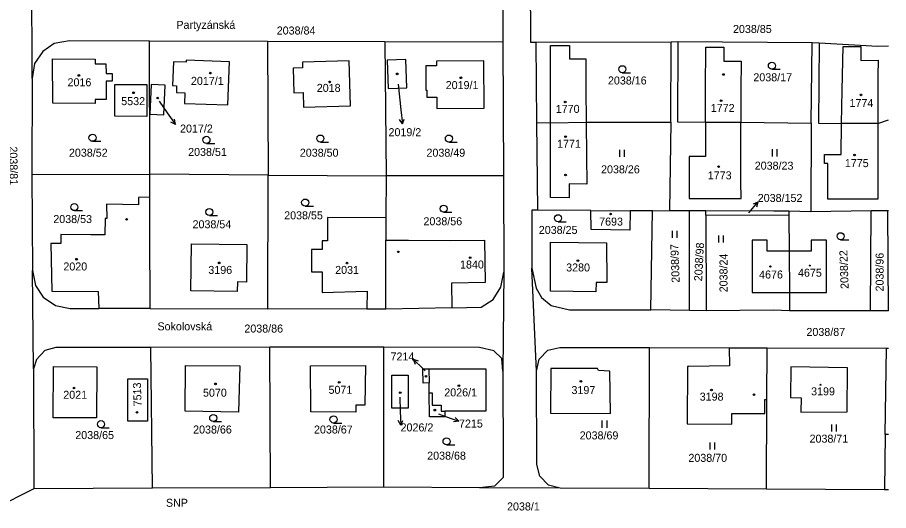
# Model space of a CAD drawing. Extents: x -667048 to -665920, y -1108425 to -1107247.
# Drawn here: x -666112.2 to -665927.3, y -1108016.4 to -1107911.7 of the extents above; entities that cross this region are included whole.
import ezdxf

# ---------------------------------------------------------------- set-up
doc = ezdxf.new("R2010")
doc.units = 0
for name, color, linetype in [('Default', 7, 'Continuous'), ('Hranice parcel', 7, 'Continuous'), ('Parcelní čísla', 7, 'Continuous'), ('Pop_ PČ_ popisy', 7, 'Continuous'), ('Značky budov', 7, 'Continuous'), ('Značky kultur', 7, 'Continuous')]:
    doc.layers.add(name, color=color, linetype=linetype)

# ---------------------------------------------------------------- blocks, each defined once
blk = doc.blocks.new('3.041')
at = {"layer": 'Default'}
blk.add_line((8, 0), (1758, 0), dxfattribs=at)
blk.add_circle((8, 750), 750, dxfattribs=at)
blk = doc.blocks.new('4.021')
at = {"layer": 'Default'}
blk.add_circle((-7, 1), 175, dxfattribs=at)
blk = doc.blocks.new('10291')
at = {"layer": 'Default'}
for p, q in [((0, 3001), (-500, 2001)), ((0, 1), (0, 3001)), ((0, 3001), (500, 2001))]:
    blk.add_line(p, q, dxfattribs=at)
blk = doc.blocks.new('3.061')
at = {"layer": 'Default'}
for p, q in [((-511, -1), (-511, 1499)), ((489, -1), (489, 1499))]:
    blk.add_line(p, q, dxfattribs=at)

msp = doc.modelspace()

# ---------------------------------------------------------------- linework, layer by layer
at = {"layer": 'Hranice parcel'}
for points in [[(-666109.14, -1107924.68), (-666109.22, -1107902.47)], [(-666009.29, -1107902.93), (-666009.17, -1107916.92)], [(-666002.18, -1107916.98), (-666003.25, -1107916.98), (-666003.34, -1107903.53), (-666002.62, -1107906.32)], [(-666084.2, -1107916.69), (-666101.19, -1107916.63), (-666104.47, -1107917.24), (-666106.87, -1107918.91), (-666108.59, -1107921.44), (-666109.14, -1107924.68)], [(-666059.15, -1107916.77), (-666084.2, -1107916.69)], [(-666084.16, -1107944.97), (-666084.2, -1107916.69)], [(-666034.24, -1107916.85), (-666059.15, -1107916.77)], [(-666059.15, -1107916.77), (-666059.02, -1107945.17)], [(-666009.17, -1107916.92), (-666034.24, -1107916.85)], [(-666034.24, -1107916.85), (-666033.99, -1107945.29)], [(-666009.17, -1107916.92), (-666009.03, -1107945.29)], [(-665973.46, -1107916.94), (-666002.18, -1107916.98)], [(-666002.18, -1107916.98), (-666002.03, -1107933.98)], [(-665973.55, -1107933.95), (-665973.46, -1107916.94)], [(-665972.08, -1107916.86), (-665973.46, -1107916.94)], [(-665972.08, -1107916.86), (-665972.13, -1107933.88), (-665966.18, -1107933.9)], [(-665943.55, -1107917.11), (-665972.08, -1107916.86)], [(-665999.1, -1107926.84), (-665999.08, -1107917.67), (-665995.07, -1107917.66), (-665995.07, -1107920.5), (-665991.58, -1107920.49), (-665991.59, -1107926.83)], [(-665966.17, -1107926.9), (-665966.09, -1107918), (-665962.27, -1107918), (-665962.27, -1107920.98), (-665958.6, -1107920.98), (-665958.67, -1107927.03)], [(-665943.74, -1107934.12), (-665943.55, -1107917.11)], [(-665942.06, -1107917.12), (-665943.55, -1107917.11)], [(-665942.06, -1107917.12), (-665942.2, -1107934.14), (-665937.28, -1107934.21)], [(-665929.62, -1107917.85), (-665942.06, -1107917.12)], [(-665937.16, -1107927.12), (-665936.98, -1107917.89), (-665933.19, -1107917.88), (-665933.24, -1107920.8), (-665929.51, -1107920.79), (-665929.57, -1107924.08)], [(-665927.32, -1107917.8), (-665929.62, -1107917.85)], [(-666092.12, -1107925.23), (-666093.43, -1107925.22), (-666093.42, -1107929.09), (-666095.72, -1107929.08), (-666095.72, -1107929.96), (-666104.73, -1107929.91), (-666104.77, -1107920.48), (-666095.76, -1107920.53), (-666095.76, -1107921.56), (-666093.45, -1107921.57), (-666093.44, -1107923.59), (-666092.13, -1107923.6), (-666092.12, -1107925.23)], [(-666029.79, -1107920.64), (-666033.74, -1107920.79)], [(-666033.74, -1107920.79), (-666033.51, -1107926.76), (-666029.56, -1107926.61), (-666029.79, -1107920.64)], [(-666076.42, -1107920.75), (-666076.44, -1107921.21), (-666079.14, -1107921.11), (-666079.32, -1107926.15), (-666078.45, -1107926.18), (-666078.5, -1107927.61), (-666076.68, -1107927.68), (-666076.76, -1107929.92), (-666067.59, -1107930.26), (-666067.25, -1107921.09)], [(-666067.25, -1107921.09), (-666076.42, -1107920.75)], [(-666051.51, -1107930.73), (-666041.56, -1107930.46), (-666041.79, -1107920.91), (-666051.74, -1107921.15), (-666051.71, -1107922.41), (-666053.72, -1107922.45), (-666053.59, -1107927.68), (-666051.58, -1107927.63), (-666051.51, -1107930.73)], [(-666013.22, -1107920.91), (-666023.27, -1107920.97), (-666023.26, -1107921.98), (-666025.58, -1107921.99), (-666025.54, -1107927.11), (-666025.34, -1107927.11), (-666025.33, -1107928.62), (-666023.22, -1107928.61), (-666023.21, -1107931.04), (-666013.16, -1107930.96), (-666013.22, -1107920.91)], [(-665929.57, -1107924.08), (-665929.58, -1107927.14), (-665929.59, -1107934.2)], [(-666109.14, -1107924.68), (-666109.16, -1107945)], [(-666084.8, -1107932.74), (-666091.6, -1107932.61), (-666091.6, -1107925.91), (-666084.8, -1107925.89), (-666084.8, -1107932.74)], [(-666081.15, -1107932.38), (-666080.88, -1107926.04), (-666083.88, -1107925.91), (-666084.15, -1107932.25), (-666081.15, -1107932.38)], [(-665999.09, -1107934.05), (-665999.1, -1107926.84)], [(-665991.59, -1107926.83), (-665991.51, -1107933.93)], [(-665966.18, -1107933.9), (-665966.17, -1107926.9)], [(-665958.67, -1107927.03), (-665958.68, -1107933.9)], [(-665937.28, -1107934.21), (-665937.16, -1107927.12)], [(-665929.59, -1107934.2), (-665927.32, -1107933.44)], [(-666002.03, -1107933.98), (-666001.86, -1107952.62)], [(-666002.03, -1107933.98), (-665999.09, -1107934.05)], [(-665999.09, -1107934.05), (-665991.51, -1107933.93)], [(-665999.08, -1107941.03), (-665999.09, -1107934.05)], [(-665991.51, -1107933.93), (-665973.55, -1107933.95)], [(-665991.51, -1107933.93), (-665991.42, -1107941.13)], [(-665973.55, -1107933.95), (-665973.84, -1107952.63)], [(-665966.18, -1107933.9), (-665966.18, -1107941.18), (-665969.64, -1107941.21), (-665969.64, -1107950.11), (-665958.63, -1107950.09)], [(-665966.18, -1107933.9), (-665958.68, -1107933.9)], [(-665958.68, -1107944.18), (-665958.68, -1107933.9)], [(-665958.68, -1107933.9), (-665943.74, -1107934.12)], [(-665943.74, -1107934.12), (-665943.83, -1107952.86)], [(-665929.59, -1107934.2), (-665929.6, -1107941.25), (-665929.61, -1107944.35), (-665929.62, -1107950.25), (-665940.22, -1107950.23), (-665940.21, -1107942.66), (-665940.95, -1107942.66), (-665940.94, -1107940.76), (-665937.38, -1107940.77), (-665937.28, -1107934.21)], [(-665929.59, -1107934.2), (-665937.28, -1107934.21)], [(-665991.42, -1107941.13), (-665991.39, -1107947.08), (-665995.13, -1107947.03), (-665995.13, -1107949.97), (-665999.05, -1107949.92), (-665999.08, -1107941.03)], [(-665958.63, -1107950.09), (-665958.66, -1107946.53), (-665958.68, -1107944.18)], [(-666109.16, -1107945), (-666084.16, -1107944.97)], [(-666109.16, -1107945), (-666109.07, -1107965.42)], [(-666084.14, -1107949.85), (-666084.16, -1107944.97)], [(-666059.02, -1107945.17), (-666084.16, -1107944.97)], [(-666059.07, -1107973.56), (-666059.02, -1107945.17)], [(-666059.02, -1107945.17), (-666033.99, -1107945.29)], [(-666033.99, -1107945.29), (-666034.02, -1107954.2)], [(-666009.03, -1107945.29), (-666033.99, -1107945.29)], [(-666009.03, -1107945.29), (-666009.01, -1107965.76)], [(-666086.54, -1107949.92), (-666086.56, -1107951.45), (-666093.33, -1107951.35), (-666093.28, -1107954.36), (-666093.64, -1107954.36)], [(-666084.14, -1107949.85), (-666086.54, -1107949.92)], [(-666084.04, -1107973.49), (-666084.11, -1107957.13), (-666084.12, -1107954.62), (-666084.14, -1107949.85)], [(-666003.03, -1107952.61), (-666003.04, -1107964.92)], [(-666001.86, -1107952.62), (-666003.03, -1107952.61)], [(-665990.55, -1107952.68), (-666001.86, -1107952.62)], [(-665990.45, -1107956.73), (-665990.55, -1107952.68)], [(-665990.55, -1107952.68), (-665982.17, -1107952.73)], [(-665982.17, -1107952.73), (-665982.21, -1107956.85)], [(-665977.46, -1107952.76), (-665982.17, -1107952.73)], [(-665977.77, -1107973.77), (-665977.46, -1107952.76)], [(-665977.46, -1107952.76), (-665973.84, -1107952.63)], [(-665973.84, -1107952.63), (-665969.55, -1107952.66)], [(-665969.58, -1107973.91), (-665969.55, -1107952.92), (-665969.55, -1107952.66)], [(-665969.55, -1107952.66), (-665966.14, -1107952.68)], [(-665966.14, -1107952.68), (-665951.66, -1107952.76), (-665948.51, -1107952.76)], [(-665966.14, -1107953.66), (-665966.14, -1107952.68)], [(-665948.5, -1107953.7), (-665966.14, -1107953.66)], [(-665966.14, -1107953.66), (-665966.07, -1107973.93)], [(-665948.51, -1107952.76), (-665943.83, -1107952.86)], [(-665948.51, -1107952.76), (-665948.5, -1107953.7)], [(-665948.5, -1107953.7), (-665948.44, -1107961.3)], [(-665943.83, -1107952.86), (-665931.04, -1107952.66)], [(-665931.12, -1107973.95), (-665931.04, -1107952.66)], [(-665931.04, -1107952.66), (-665927.54, -1107952.63)], [(-665927.54, -1107952.63), (-665927.41, -1107973.99)], [(-665927.54, -1107952.63), (-665927.32, -1107952.63)], [(-666093.64, -1107954.36), (-666093.66, -1107957.85), (-666096.65, -1107957.83), (-666103.04, -1107957.79), (-666103, -1107959.67), (-666105.16, -1107959.65), (-666104.92, -1107969.82), (-666095.08, -1107969.88), (-666094.97, -1107973.46)], [(-666034.02, -1107954.2), (-666046.44, -1107954.17), (-666046.43, -1107959.11), (-666047.54, -1107959.12), (-666047.54, -1107960.95), (-666049.79, -1107960.95), (-666049.79, -1107965.7), (-666047.54, -1107965.7), (-666047.54, -1107970.07)], [(-666034.02, -1107954.2), (-666034.03, -1107958.93)], [(-665982.21, -1107956.85), (-665990.45, -1107956.73)], [(-666034.07, -1107973.63), (-666034.03, -1107958.93)], [(-666034.03, -1107958.93), (-666033.48, -1107958.93), (-666029.22, -1107958.96), (-666020.22, -1107959.01), (-666013.09, -1107958.96), (-666012.94, -1107967.97), (-666020.1, -1107968.09)], [(-665999.09, -1107959.37), (-665987.19, -1107959.55), (-665987.15, -1107967.98), (-665989.4, -1107967.95), (-665989.43, -1107969.92), (-665999.08, -1107969.78), (-665999.09, -1107959.37)], [(-665948.44, -1107961.3), (-665953.1, -1107961.32), (-665953.1, -1107958.96), (-665956.26, -1107958.96), (-665956.27, -1107970.09), (-665948.37, -1107970.1)], [(-665948.37, -1107970.1), (-665940.52, -1107970.1), (-665940.51, -1107958.96), (-665943.78, -1107958.95), (-665943.78, -1107961.27), (-665948.44, -1107961.3)], [(-666075.4, -1107969.75), (-666075.27, -1107959.71), (-666063.52, -1107959.89), (-666063.62, -1107967.87), (-666065.55, -1107967.84), (-666065.58, -1107969.89), (-666075.4, -1107969.75)], [(-665948.44, -1107961.3), (-665948.37, -1107970.1)], [(-666002.07, -1107986.79), (-666003.04, -1107964.92)], [(-666003.04, -1107964.92), (-666002.12, -1107969.12), (-666001, -1107971.11), (-665998.96, -1107972.82), (-665995.02, -1107973.72)], [(-666108.85, -1107986.29), (-666109.07, -1107965.42)], [(-666109.07, -1107965.42), (-666108.4, -1107968.6), (-666106.75, -1107971.04), (-666104.19, -1107972.83), (-666101.05, -1107973.45)], [(-666013.79, -1107973.17), (-666011.27, -1107971.57), (-666009.66, -1107968.93), (-666009.01, -1107965.76)], [(-666009.01, -1107965.76), (-666009.21, -1107986.77)], [(-666020.1, -1107968.09), (-666020.05, -1107973.31)], [(-666047.54, -1107970.07), (-666038.02, -1107969.82)], [(-666038.02, -1107969.82), (-666038.04, -1107973.62)], [(-665948.37, -1107970.1), (-665948.34, -1107973.94)], [(-666101.05, -1107973.45), (-666094.97, -1107973.46)], [(-666084.04, -1107973.49), (-666094.97, -1107973.46)], [(-666084.04, -1107973.49), (-666059.07, -1107973.56)], [(-666038.04, -1107973.62), (-666059.07, -1107973.56)], [(-666034.07, -1107973.63), (-666038.04, -1107973.62)], [(-666020.05, -1107973.31), (-666034.07, -1107973.63)], [(-666020.05, -1107973.31), (-666013.79, -1107973.17)], [(-665995.02, -1107973.72), (-665977.77, -1107973.77)], [(-665969.58, -1107973.91), (-665977.77, -1107973.77)], [(-665966.07, -1107973.93), (-665969.58, -1107973.91)], [(-665948.34, -1107973.94), (-665951.76, -1107973.84), (-665966.07, -1107973.93)], [(-665931.12, -1107973.95), (-665948.34, -1107973.94)], [(-665927.41, -1107973.99), (-665931.12, -1107973.95)], [(-665927.32, -1107973.99), (-665927.41, -1107973.99)], [(-666083.89, -1107981.72), (-666104.08, -1107981.74), (-666106.46, -1107982.37), (-666108.23, -1107984.27), (-666108.85, -1107986.29)], [(-666058.67, -1107981.7), (-666083.89, -1107981.72)], [(-666083.6, -1108011.61), (-666083.89, -1107981.72)], [(-666034.47, -1107981.68), (-666058.67, -1107981.7)], [(-666058.5, -1108011.51), (-666058.67, -1107981.7)], [(-666009.21, -1107986.77), (-666009.42, -1107984.05), (-666011.1, -1107982.43), (-666014.19, -1107981.71), (-666034.47, -1107981.68)], [(-666034.44, -1108011.42), (-666034.47, -1107981.68)], [(-666002.07, -1107986.79), (-666001.49, -1107984.25), (-665999.63, -1107982.34), (-665997.12, -1107981.74), (-665978.07, -1107981.77)], [(-665978.17, -1108011.7), (-665978.07, -1107981.77)], [(-665978.07, -1107981.77), (-665961.19, -1107981.78)], [(-665961.19, -1107981.78), (-665961.08, -1107985.66), (-665969.7, -1107985.76), (-665970, -1107985.75), (-665970.08, -1107997.92), (-665960.61, -1107998), (-665960.6, -1107995.74), (-665958.91, -1107995.75), (-665953.62, -1107995.78), (-665953.59, -1107992.75), (-665953.17, -1107992.75)], [(-665961.19, -1107981.78), (-665953.12, -1107981.79)], [(-665953.17, -1107992.75), (-665953.12, -1107981.79)], [(-665953.12, -1107981.79), (-665927.74, -1107981.85)], [(-665928.02, -1108000.18), (-665927.74, -1107981.85)], [(-665927.74, -1107981.85), (-665927.32, -1107981.85)], [(-666108.85, -1107986.29), (-666108.73, -1108011.71)], [(-666095.43, -1107996.69), (-666104.63, -1107996.64), (-666104.57, -1107985.79), (-666095.37, -1107985.84), (-666095.43, -1107996.69)], [(-666076.6, -1107985.58), (-666065, -1107985.65), (-666065.33, -1107995.5), (-666076.66, -1107995.22), (-666076.6, -1107985.58)], [(-666040.38, -1107995.44), (-666049.93, -1107995.41), (-666050, -1107985.65), (-666038.37, -1107985.57), (-666038.5, -1107993.96), (-666040.38, -1107993.96), (-666040.38, -1107995.44)], [(-666026.15, -1107986.26), (-666024.92, -1107986.24)], [(-666026.14, -1107989.28), (-666026.15, -1107986.26)], [(-666024.92, -1107986.24), (-666012.81, -1107986.26), (-666012.81, -1107995.29), (-666021.51, -1107995.29)], [(-666024.92, -1107986.24), (-666024.87, -1107989.27)], [(-666009.21, -1107986.77), (-666009.11, -1108006.53), (-666009.11, -1108009.34), (-666010.97, -1108011.14), (-666014.16, -1108011.52)], [(-666001.99, -1108006.59), (-666002.07, -1107986.79)], [(-665989.11, -1107986.17), (-665999.03, -1107986.22), (-665999.09, -1107995.66), (-665986.35, -1107995.74), (-665986.52, -1107986.77), (-665988.92, -1107986.65), (-665989.11, -1107986.17)], [(-665948.05, -1107985.85), (-665948.15, -1107992.37), (-665945.88, -1107992.41), (-665945.92, -1107995.44), (-665936.09, -1107995.4), (-665936.06, -1107986.04), (-665948.05, -1107985.85)], [(-666084.66, -1107988.4), (-666084.61, -1107997.38), (-666088.79, -1107997.4), (-666088.84, -1107988.36), (-666084.66, -1107988.4)], [(-666029.27, -1107994.64), (-666032.76, -1107994.63), (-666032.76, -1107987.58), (-666029.27, -1107987.59), (-666029.27, -1107994.64)], [(-666024.87, -1107989.27), (-666026.14, -1107989.28)], [(-666024.84, -1107991.33), (-666024.87, -1107989.27)], [(-666024.84, -1107991.33), (-666024.21, -1107991.33), (-666024.19, -1107994), (-666022.29, -1107994), (-666022.3, -1107995.28), (-666021.51, -1107995.29)], [(-666024.79, -1107996.48), (-666024.84, -1107991.33)], [(-665953.26, -1108011.81), (-665953.17, -1107992.75)], [(-666021.48, -1107996.47), (-666024.79, -1107996.48)], [(-666021.51, -1107995.29), (-666021.48, -1107996.47)], [(-665928.02, -1108000.18), (-665928.2, -1108011.92)], [(-665927.32, -1108000.19), (-665928.02, -1108000.18)], [(-665997.01, -1108011.61), (-665999.52, -1108010.99), (-666001.37, -1108009.08), (-666001.99, -1108006.59)], [(-666108.73, -1108011.71), (-666116.97, -1108015.85)], [(-666083.6, -1108011.61), (-666108.73, -1108011.71)], [(-666058.5, -1108011.51), (-666083.6, -1108011.61)], [(-666034.44, -1108011.42), (-666058.5, -1108011.51)], [(-666014.16, -1108011.52), (-666034.44, -1108011.42)], [(-665997.01, -1108011.61), (-666014.16, -1108011.52)], [(-665978.17, -1108011.7), (-665997.01, -1108011.61)], [(-665953.26, -1108011.81), (-665978.17, -1108011.7)], [(-665928.2, -1108011.92), (-665953.26, -1108011.81)], [(-665927.32, -1108011.93), (-665928.2, -1108011.92)]]:
    msp.add_lwpolyline(points, dxfattribs=at)
at = {"layer": 'Pop_ PČ_ popisy'}
for points in [[(-666031.39, -1107925.86), (-666030.82, -1107931.32)], [(-666082.18, -1107929.45), (-666080.43, -1107931.96)], [(-666025.69, -1107986.67), (-666026.06, -1107986.31)], [(-666031.08, -1107992.3), (-666030.97, -1107995.22)], [(-666022.84, -1107995.84), (-666021.39, -1107996.37)]]:
    msp.add_lwpolyline(points, dxfattribs=at)

# ---------------------------------------------------------------- block references
for p, xscale, yscale, rotation in [((-666080.43, -1107931.96), 0.0010000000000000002, 0.0010000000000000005, -145.0000000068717), ((-666030.82, -1107931.32), 0.0010000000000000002, 0.001, -174.00000001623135), ((-665957, -1107953.16), 0.0010000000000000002, 0.0010000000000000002, -39.9999999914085), ((-666026.06, -1107986.31), 0.001, 0.0010000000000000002, 45.99999999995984), ((-666030.97, -1107995.22), 0.001, 0.0010000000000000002, -177.99999998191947), ((-666021.39, -1107996.37), 0.001, 0.0010000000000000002, -109.99999998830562)]:
    msp.add_blockref('10291', p, dxfattribs=dict(at, xscale=xscale, yscale=yscale, rotation=rotation))
at = {"layer": 'Značky budov'}
for p, xscale, yscale in [((-666099.2, -1107924.01), 0.0010000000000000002, 0.0010000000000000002), ((-666071.3, -1107923.5), 0.0010000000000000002, 0.0010000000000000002), ((-666031.62, -1107923.67), 0.0010000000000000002, 0.0010000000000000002), ((-666018.1, -1107924.49), 0.0010000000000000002, 0.0010000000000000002), ((-665962.36, -1107923.8), 0.0010000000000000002, 0.0010000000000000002), ((-666045.97, -1107925.36), 0.0010000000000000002, 0.0010000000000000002), ((-666087.59, -1107927.68), 0.0010000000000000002, 0.0010000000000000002), ((-665933.16, -1107928.13), 0.0010000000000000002, 0.0010000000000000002), ((-666082.46, -1107928.79), 0.0010000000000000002, 0.0010000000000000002), ((-665995.95, -1107929.62), 0.0010000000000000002, 0.0010000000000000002), ((-665962.86, -1107929.37), 0.0010000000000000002, 0.0010000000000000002), ((-665995.89, -1107937), 0.0010000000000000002, 0.0010000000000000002), ((-665934.53, -1107940.9), 0.0010000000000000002, 0.0010000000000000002), ((-665963.38, -1107943.35), 0.0010000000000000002, 0.0010000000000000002), ((-665995.89, -1107945.14), 0.0010000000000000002, 0.0010000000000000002), ((-665986.31, -1107953.41), 0.0010000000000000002, 0.0010000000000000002), ((-666089.06, -1107954.55), 0.0010000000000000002, 0.0010000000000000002), ((-666031.39, -1107961.44), 0.0010000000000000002, 0.0010000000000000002), ((-666099.69, -1107963.01), 0.0010000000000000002, 0.0010000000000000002), ((-666016.13, -1107962.69), 0.0010000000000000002, 0.0010000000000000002), ((-665993.26, -1107963.33), 0.0010000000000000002, 0.0010000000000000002), ((-666069.41, -1107963.78), 0.0010000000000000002, 0.0010000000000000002), ((-666042.26, -1107963.84), 0.0010000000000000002, 0.0010000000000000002), ((-665952.41, -1107964.55), 0.0006700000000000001, 0.0006700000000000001), ((-665944.04, -1107964.36), 0.0006700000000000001, 0.0006700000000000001), ((-666043.93, -1107989.15), 0.0010000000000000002, 0.0010000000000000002), ((-666025.5, -1107987.84), 0.0010000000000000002, 0.0010000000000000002), ((-665992.63, -1107988.94), 0.0010000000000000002, 0.0010000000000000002), ((-666100.22, -1107990.34), 0.0010000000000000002, 0.0010000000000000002), ((-666070.2, -1107989.47), 0.0010000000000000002, 0.0010000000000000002), ((-666018.53, -1107989.83), 0.0010000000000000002, 0.0010000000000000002), ((-665964.91, -1107990.77), 0.0010000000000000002, 0.0010000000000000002), ((-665941.77, -1107989.65), 0.0006700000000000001, 0.0006700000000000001), ((-666030.98, -1107991.33), 0.0010000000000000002, 0.0010000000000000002), ((-665955.88, -1107991.76), 0.0010000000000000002, 0.0010000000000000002), ((-666086.87, -1107995.51), 0.0010000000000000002, 0.0010000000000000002), ((-666023.64, -1107995.03), 0.0010000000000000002, 0.0010000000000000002)]:
    msp.add_blockref('4.021', p, dxfattribs=dict(at, xscale=xscale, yscale=yscale))
at = {"layer": 'Značky kultur', "xscale": 0.0010000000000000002, "yscale": 0.0010000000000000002}
for name, p in [('3.041', (-665983.85, -1107923.43)), ('3.041', (-665952.1, -1107922.69)), ('3.041', (-666096.31, -1107937.98)), ('3.041', (-666072.13, -1107938.42)), ('3.041', (-666047.95, -1107938.14)), ('3.041', (-666020.66, -1107938.14)), ('3.061', (-665983.85, -1107941.3)), ('3.061', (-665951.48, -1107941.18)), ('3.041', (-666051.17, -1107951.73)), ('3.041', (-666100.16, -1107952.69)), ('3.041', (-666021.78, -1107953.03)), ('3.041', (-666071.51, -1107953.74)), ('3.041', (-665997.49, -1107955.06)), ('3.061', (-665972.68, -1107958.47)), ('3.041', (-665937.51, -1107958.87)), ('3.061', (-665962.87, -1107959.49)), ('3.041', (-666070.69, -1107997.46)), ('3.041', (-666045.15, -1107997.77)), ('3.041', (-666094.52, -1107998.76)), ('3.061', (-665987.57, -1107998.77)), ('3.061', (-665938.83, -1107999.58)), ('3.041', (-666021.16, -1108002.42)), ('3.061', (-665964.71, -1108003.37))]:
    msp.add_blockref(name, p, dxfattribs=at)

# ---------------------------------------------------------------- texts
at = {"layer": 'Parcelní čísla'}
for s, p in [('2038/85', (-665960.34, -1107914.99)), ('2038/84', (-666057.2, -1107915.31)), ('2017/1', (-666075.41, -1107926)), ('2038/16', (-665986.89, -1107925.92)), ('2038/17', (-665956.02, -1107925.24)), ('2016', (-666101.61, -1107926.3)), ('2018', (-666048.7, -1107927.49)), ('2019/1', (-666021.33, -1107926.9)), ('5532', (-666090.21, -1107930.3)), ('1774', (-665935.61, -1107930.7)), ('1770', (-665997.97, -1107931.95)), ('1772', (-665965.06, -1107931.75)), ('2017/2', (-666077.72, -1107936.12)), ('2019/2', (-666033.47, -1107936.89)), ('1771', (-665997.68, -1107939.34)), ('2038/52', (-666101.31, -1107941.25)), ('2038/51', (-666076.01, -1107941.09)), ('2038/50', (-666052.3, -1107941.25)), ('2038/49', (-666025.41, -1107941.25)), ('2038/23', (-665955.73, -1107944)), ('1775', (-665936.6, -1107943.46)), ('2038/26', (-665988.35, -1107944.78)), ('1773', (-665965.7, -1107946.05)), ('2038/152', (-665955.09, -1107950.85)), ('2038/53', (-666104.63, -1107955.33)), ('2038/55', (-666055.62, -1107954.54)), ('2038/56', (-666026.05, -1107955.8)), ('2038/54', (-666075.07, -1107956.44)), ('2038/25', (-666001.57, -1107957.64)), ('7693', (-665988.76, -1107955.87)), ('1840', (-666018.29, -1107964.98)), ('2020', (-666102.49, -1107965.39)), ('3196', (-666071.72, -1107966.13)), ('2031', (-666044.8, -1107966.13)), ('3280', (-665995.76, -1107965.6)), ('4675', (-665946.55, -1107966.72)), ('4676', (-665954.8, -1107967.1)), ('2038/86', (-666064.07, -1107978.57)), ('2038/87', (-665944.75, -1107979.29)), ('7214', (-666033.04, -1107984.5)), ('2021', (-666102.51, -1107992.63)), ('5070', (-666072.85, -1107992.18)), ('5071', (-666046.21, -1107991.57)), ('2026/1', (-666021.63, -1107992.12)), ('3197', (-665994.63, -1107991.63)), ('3199', (-665943.76, -1107991.9)), ('3198', (-665967.41, -1107993.02)), ('2038/66', (-666074.95, -1108000)), ('2038/67', (-666049.29, -1108000)), ('2026/2', (-666030.91, -1107999.55)), ('7215', (-666018.51, -1107998.73)), ('2038/65', (-666099.96, -1108001.18)), ('2038/69', (-665992.89, -1108001.25)), ('2038/71', (-665944.09, -1108001.94)), ('2038/68', (-666025.26, -1108005.55)), ('2038/70', (-665969.81, -1108006.01)), ('2038/1', (-666008.31, -1108016.33))]:
    msp.add_text(s, height=1.7, dxfattribs=at).set_placement(p)
for s, rotation, p in [('2038/81', 271, (-666113.98, -1107939.08)), ('2038/98', 87, (-665966.91, -1107967.72)), ('2038/97', 92, (-665971.66, -1107967.97)), ('2038/22', 92, (-665935.79, -1107969.28)), ('2038/24', 90, (-665961.51, -1107970.03)), ('2038/96', 90, (-665928.37, -1107969.85)), ('7513', 92, (-666085.87, -1107994.21))]:
    msp.add_text(s, height=1.7, rotation=rotation, dxfattribs=at).set_placement(p)
at = {"layer": 'Pop_ PČ_ popisy'}
for s, p in [('Partyzánská', (-666078.5, -1107914.11)), ('Sokolovská', (-666082.52, -1107978.1)), ('SNP', (-666080.72, -1108015.55))]:
    msp.add_text(s, height=1.7, dxfattribs=at).set_placement(p)

doc.saveas('drawing.dxf')
